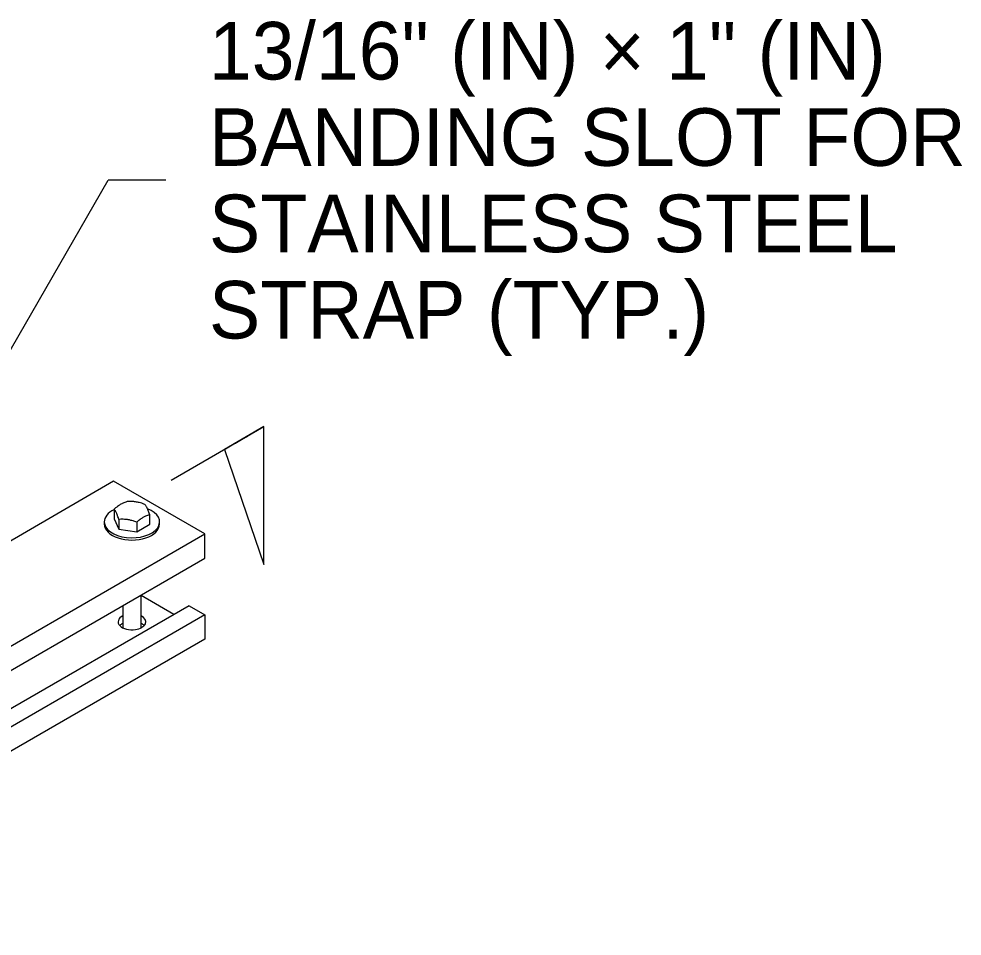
# Model space of a CAD drawing. Extents: x 99862 to 103680, y 99470 to 102076.
# Drawn here: x 100387.4 to 100649.7, y 100719.5 to 100974.5 of the extents above; entities that cross this region are included whole.
import ezdxf

# ---------------------------------------------------------------- set-up
doc = ezdxf.new("R2010")
doc.units = 0
for name, color, linetype in [('Level 1', 7, 'Continuous'), ('Level 15', 7, 'Continuous'), ('Level 20', 7, 'Continuous'), ('Level 4', 7, 'Continuous'), ('Level 5', 7, 'Continuous')]:
    doc.layers.add(name, color=color, linetype=linetype)

msp = doc.modelspace()

# ---------------------------------------------------------------- linework, layer by layer
at = {"layer": 'Level 1'}
for p, q in [((100296.08, 100748.76), (100439.08, 100831.32)), ((100296.08, 100742), (100439.08, 100824.56)), ((100430.49, 100808.93), (100421.38, 100814.17)), ((100434.69, 100811.36), (100291.7, 100728.8)), ((100439.08, 100808.82), (100296.08, 100726.27))]:
    msp.add_line(p, q, dxfattribs=at)
for points in [[(100439.08, 100824.56), (100439.08, 100831.32), (100413.74, 100845.95), (100382.1, 100827.68)], [(100434.69, 100811.36), (100439.08, 100808.82), (100439.08, 100802.06), (100296.08, 100719.52)]]:
    msp.add_lwpolyline(points, dxfattribs=at)
for centre, major_axis, start_param, end_param in [((100418.82, 100834.68), (-7.68, 0), 6.283185, 10.399537), ((100418.82, 100834.68), (-7.68, 0), 5.41204, 6.283185), ((100418.82, 100834.06), (-7.68, 0), 6.283185, 9.424778), ((100418.82, 100806.89), (3.84, 0), 2.300524, 4.96298), ((100418.82, 100806.89), (3.84, 0), 4.96298, 7.124254), ((100418.82, 100804.8), (-3.84, 0), 5.442117, 5.792303), ((100418.82, 100804.8), (-3.84, 0), 3.632475, 3.982661)]:
    msp.add_ellipse(centre, major_axis=major_axis, ratio=0.57735, start_param=start_param, end_param=end_param, dxfattribs=at)
at = {"layer": 'Level 15'}
for p in [(100362.38, 100843.21), (100428.23, 100929.65)]:
    msp.add_line(p, (100412.23, 100929.65), dxfattribs=at)
at = {"layer": 'Level 20'}
msp.add_line((100429.69, 100846.24), (100455.52, 100861.15), dxfattribs=at)
msp.add_lwpolyline([(100455.52, 100861.15), (100444.54, 100854.82), (100455.52, 100822.87), (100455.52, 100861.15)], dxfattribs=at)
msp.add_open_spline([(100443.41, 100854.16), (100447.16, 100856.33), (100450.91, 100858.49)], degree=2, dxfattribs=at)
at = {"layer": 'Level 4'}
for p, q in [((100413.88, 100838.21), (100413.88, 100835.53)), ((100413.88, 100835.53), (100415.2, 100832.67)), ((100423.77, 100834), (100423.77, 100836.68)), ((100415.2, 100835.36), (100415.2, 100832.67)), ((100420.15, 100834.59), (100420.15, 100831.91)), ((100420.15, 100831.91), (100423.77, 100834)), ((100415.2, 100832.67), (100420.15, 100831.91)), ((100421.38, 100805.24), (100421.38, 100814.34)), ((100416.26, 100811.39), (100416.26, 100805.24))]:
    msp.add_line(p, q, dxfattribs=at)
for points in [[(100417.5, 100840.3), (100417.2, 100840.22), (100416.9, 100840.13), (100416.3, 100839.88), (100415.99, 100839.73), (100415.53, 100839.47), (100415.38, 100839.37), (100415.07, 100839.17), (100414.62, 100838.84), (100414.17, 100838.47), (100413.88, 100838.21)], [(100415.2, 100835.36), (100415.09, 100835.69), (100414.93, 100836.15), (100414.76, 100836.57), (100414.65, 100836.84), (100414.6, 100836.97), (100414.43, 100837.33), (100414.32, 100837.54), (100414.1, 100837.91), (100413.99, 100838.07), (100413.88, 100838.21)], [(100422.44, 100839.54), (100422.04, 100839.69), (100421.63, 100839.83), (100420.81, 100840.06), (100420.39, 100840.16), (100419.76, 100840.25), (100419.55, 100840.28), (100419.14, 100840.32), (100418.51, 100840.35), (100417.9, 100840.33), (100417.5, 100840.3)], [(100423.77, 100836.68), (100423.66, 100837.01), (100423.55, 100837.32), (100423.33, 100837.9), (100423.22, 100838.17), (100423.05, 100838.53), (100422.99, 100838.65), (100422.88, 100838.86), (100422.71, 100839.16), (100422.55, 100839.4), (100422.44, 100839.54)], [(100420.15, 100834.59), (100419.74, 100834.75), (100419.13, 100834.96), (100418.51, 100835.11), (100418.09, 100835.21), (100417.88, 100835.25), (100417.25, 100835.34), (100416.84, 100835.38), (100416.01, 100835.4), (100415.61, 100835.39), (100415.2, 100835.36)], [(100423.77, 100836.68), (100423.47, 100836.61), (100423.17, 100836.51), (100422.56, 100836.26), (100422.26, 100836.12), (100421.8, 100835.85), (100421.65, 100835.75), (100421.34, 100835.55), (100420.88, 100835.22), (100420.44, 100834.85), (100420.15, 100834.59)]]:
    msp.add_open_spline(points, degree=3, dxfattribs=at)
at = {"layer": 'Level 5'}
for p, q in [((100411.14, 100834.68), (100411.14, 100834.06)), ((100426.5, 100834.06), (100426.5, 100834.68))]:
    msp.add_line(p, q, dxfattribs=at)

# ---------------------------------------------------------------- texts
at = {"layer": 'Level 20'}
for s, p in [('13/16" (IN) × 1" (IN) ', (100440.23, 100957.65)), ('BANDING SLOT FOR ', (100440.23, 100933.65)), ('STAINLESS STEEL ', (100440.23, 100909.65)), ('STRAP (TYP.)', (100440.23, 100885.65))]:
    msp.add_text(s, height=16, dxfattribs=at).set_placement(p)

doc.saveas('drawing.dxf')
